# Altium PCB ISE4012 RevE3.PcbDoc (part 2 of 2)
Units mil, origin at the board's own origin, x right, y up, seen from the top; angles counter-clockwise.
Board outline 4950 x 3450 mil, 4 copper layers (Top Layer, InternalPlane1, MidLayer1, Bottom Layer), stack 59 mil thick; 143 components, 94 nets, 413 pads, 604 vias.
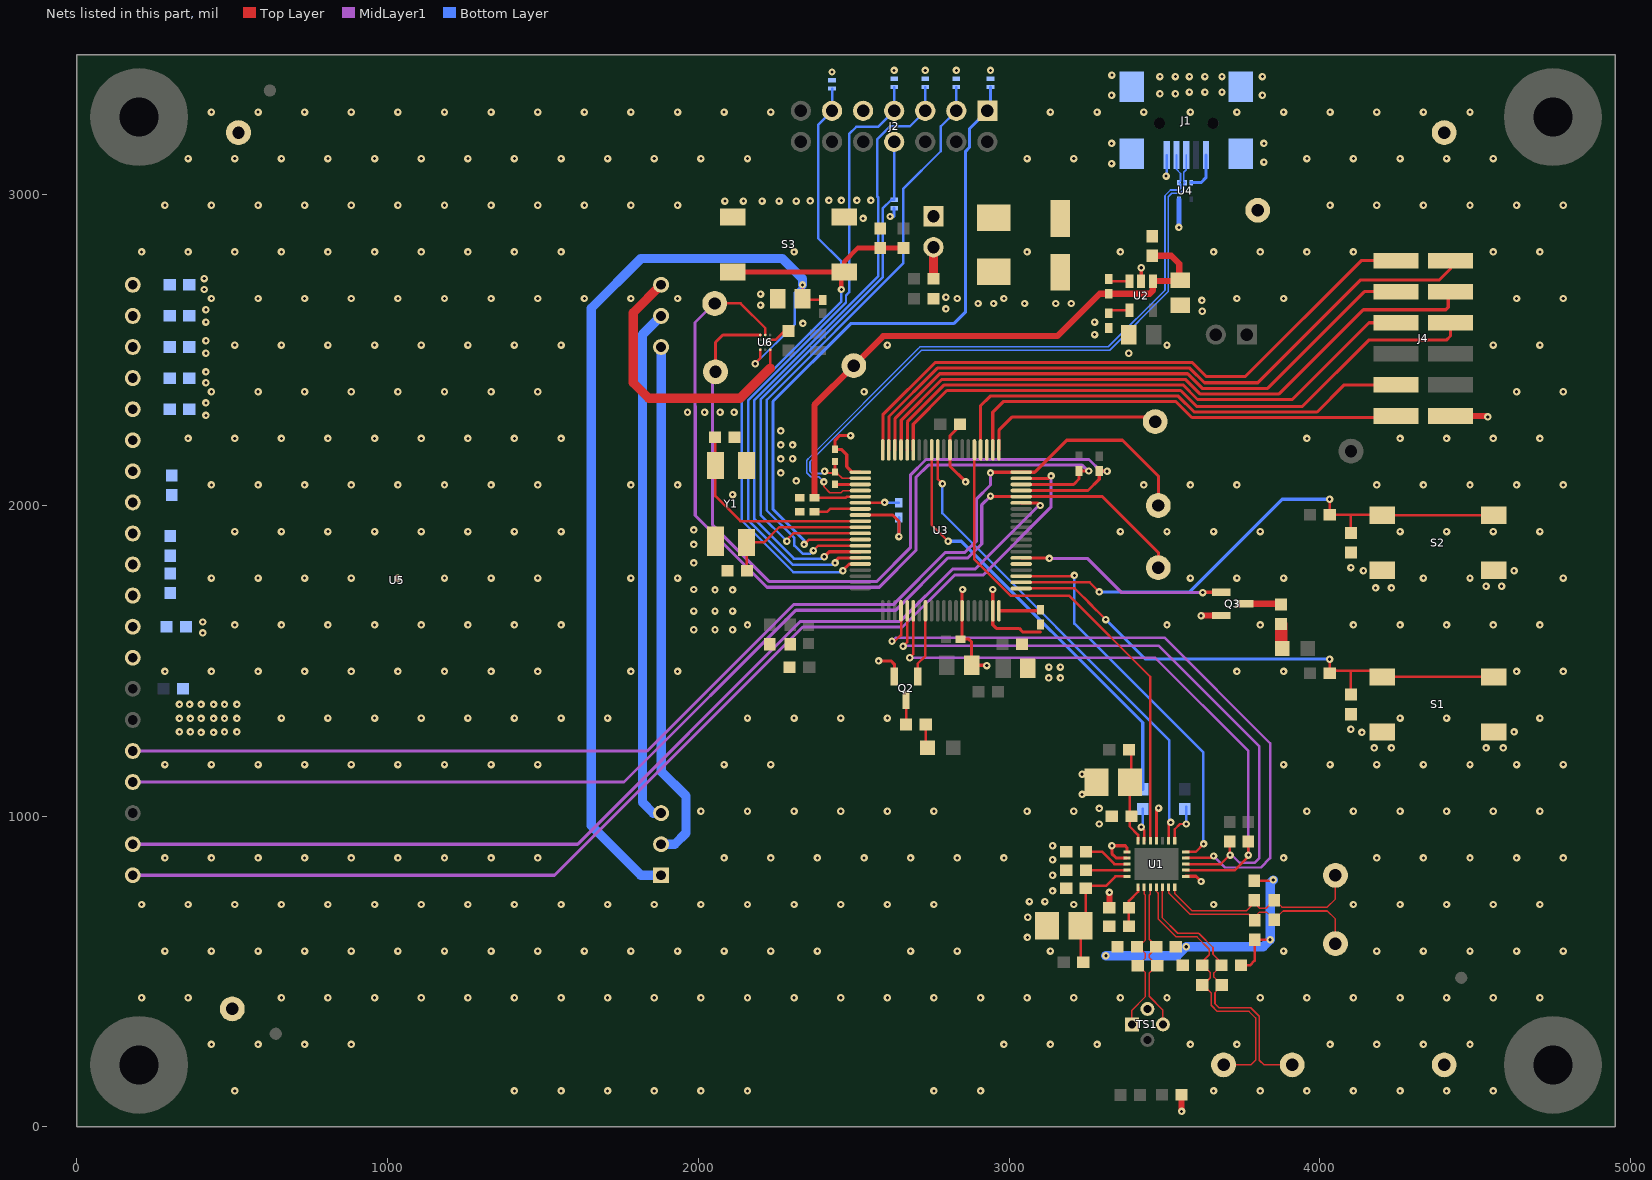
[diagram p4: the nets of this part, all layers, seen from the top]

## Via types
v1: diameter 24, hole 10, Top Layer to Bottom Layer, 393 vias
v2: diameter 24, hole 10, Top Layer to Bottom Layer, tented both sides, 210 vias
v3: diameter 24/24/24 (per signal layer), hole 10, Top Layer to Bottom Layer, tented both sides, 1 vias

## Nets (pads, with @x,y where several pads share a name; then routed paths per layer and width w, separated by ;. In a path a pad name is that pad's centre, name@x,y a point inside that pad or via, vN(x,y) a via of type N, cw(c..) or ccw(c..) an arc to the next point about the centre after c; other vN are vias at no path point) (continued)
GND: C1.2 C2.2 C3.2 C4.1 C5.2 C9.2 C10.2 C11.2 C12.2 C13.2 C14.2 C15.2 C16.2 C17.2 C18.2 C19.2 C20.2 C21.2 C22.2 C23.2 C24.2 C25.2 C26.2 C27.2 C28.2 C29.2 C30.2 C31.2 C35.2 C36.2 C37.2 C38.2 C39.2 C40.2 C41.2 C42.2 C43.2 C44.2 D1.2 D5.2 D6.2 D7.2 D8.2 D9.2 D10.2 J1.5 J1.6 J1.7 J1.8 J1.9 J2.9 J4.12 Q2.2 Q3.2 R16.1 R24.2 S1.3 S1.4 S2.3 S2.4 S3.3 S3.4 TP1.1 TP2.1 TP3.1 TP4.1 TS1.4 U1.8 U1.16 U1.20 U1.21 U2.2 U3.14 U3.19 U3.49 U3.61 U3.68 U4.3 U5.26 U5.33 U6.B3 U6.C2 Y1.2 Y1.4 | length 2288.9
  Top Layer w5: U6.C2@2214.5,2517.13 U6.B3@2230.25,2532.87
  Top Layer w8: U6.B3@2230.25,2532.87 2247.87,2532.87 2281.5,2566.5 C41.2@2295,2566.5
  Top Layer w10: v2(2490,2225) 2455,2225 2440,2210 R24.2@2440,2180.69 2460.27,2180.69 2477.27,2163.68 2477.27,2125 2495.26,2107.01 U3.61@2521.14,2107.01 ; U3.68@2521.14,1969.21 2625.79,1969.21 2645,1950 v2(2645,1900) ; v2(2580,1500) 2620,1500 2630.79,1489.21 Q2.2@2630.79,1449.48 ; C27.2@2841.5,2261 2841.5,2256.5 2809.53,2224.53 U3.49@2809.53,2178.86 2809.53,2126.47 v2(2860,2076) ; v2(2850,1729.61) 2848.9,1728.5 U3.14@2848.9,1661.14 2848.9,1575.28 C28.2@2843.62,1570 2870.5,1570 2879,1561.5 C29.2@2879,1486 2923.5,1486 v2@2928,1481.5 ; v2(2947.32,1729.61) U3.19@2947.32,1661.14 2947.32,1616 2958.82,1604.5 3032,1604.5 3043.12,1593.38 3101,1593.38 ; U1.21@3379.45,865.75 3344.25,865.75 3330.5,879.5 v2(3330.5,905) 3373.5,905 3379.45,899.05 U1.20@3379.45,885.43 ; U2.2@3425,2722.24 v2(3425,2765) ; U1.16@3473.94,920.87 3473.94,1018.94 v2(3481,1026) ; U1.8@3568.43,806.69 3601.15,806.69 v2(3617.84,790)
  Top Layer w20: C5.2@3322.44,706.06 3322.5,706.13 v2(3322.5,755) ; C44.2@3554.5,104 3555,103.5 v2(3555,50) ; v2(3617.5,1645) 3618.6,1646.1 Q3.2@3682.6,1646.1 ; J4.12@4420.5,2288 4537,2288 v2(4540,2285)
  Bottom Layer w10: v2(2617.1,2930) 2628.5,2930 2630,2931.5 D9.2@2630,2956.61 ; v2(2645,1900) C24.2@2645,1961.38 ; U4.3@3586.19,3039.07 3617.35,3039.07 3632.99,3054.71 J1.5@3632.99,3127.64
  other v1: 508,116 1408,116 1558,116 1708,116 1858,116 2008,116 2158,116 2758,116 2908,116 3658,116 3808,116 3958,116 4108,116 4258,116 4408,116 4558,116 433,266 583,266 733,266 883,266 2983,266 3133,266 3283,266 3583,266 3733,266 4033,266 4183,266 4333,266 4483,266 208,416 358,416 658,416 808,416 958,416 1108,416 1258,416 1408,416 1558,416 1708,416 1858,416 2008,416 2158,416 2308,416 2458,416 2608,416 2758,416 2908,416 3058,416 3208,416 3358,416 3508,416 3808,416 3958,416 4108,416 4258,416 4408,416 4558,416 4708,416 283,566 433,566 583,566 733,566 883,566 1033,566 1183,566 1333,566 1483,566 1633,566 1783,566 1933,566 2083,566 2233,566 2383,566 2683,566 2833,566 3133,566 3883,566 4183,566 4333,566 4483,566 4633,566 4783,566 208,716 358,716 508,716 658,716 808,716 958,716 1108,716 1258,716 1408,716 1558,716 1708,716 1858,716 2008,716 2158,716 2308,716 2458,716 2608,716 2758,716 3208,716 3658,716 4108,716 4258,716 4408,716 4558,716 4708,716 283,866 433,866 583,866 733,866 883,866 1033,866 1183,866 1333,866 1483,866 2083,866 2233,866 2383,866 2533,866 2683,866 2833,866 2983,866 3883,866 4183,866 4333,866 4483,866 4633,866 4783,866 2008,1016 2158,1016 2308,1016 2458,1016 2608,1016 2758,1016 3058,1016 3208,1016 3958,1016 4108,1016 4258,1016 4408,1016 4558,1016 4708,1016 283,1166 433,1166 583,1166 733,1166 883,1166 1033,1166 1183,1166 1333,1166 1483,1166 2083,1166 2233,1166 3883,1166 4033,1166 4183,1166 4333,1166 4483,1166 4633,1166 4783,1166 658,1316 808,1316 958,1316 1108,1316 1258,1316 1408,1316 1558,1316 1708,1316 2158,1316 2308,1316 2458,1316 2608,1316 4258,1316 4408,1316 4708,1316 283,1466 433,1466 583,1466 733,1466 883,1466 1033,1466 1183,1466 1333,1466 1483,1466 1783,1466 1933,1466 3733,1466 3883,1466 4633,1466 4783,1466 508,1616 658,1616 808,1616 958,1616 1108,1616 1258,1616 1408,1616 1558,1616 2158,1616 3508,1616 3808,1616 4108,1616 4258,1616 4408,1616 4558,1616 4708,1616 433,1766 583,1766 733,1766 883,1766 1033,1766 1183,1766 1333,1766 1483,1766 1783,1766 1933,1766 3583,1766 3733,1766 3883,1766 4333,1766 4483,1766 4783,1766 508,1916 658,1916 808,1916 958,1916 1108,1916 1258,1916 1408,1916 1558,1916 3358,1916 3508,1916 3658,1916 3808,1916 4258,1916 4408,1916 4558,1916 4708,1916 433,2066 583,2066 733,2066 883,2066 1033,2066 1183,2066 1333,2066 1483,2066 1783,2066 1933,2066 3433,2066 3583,2066 3733,2066 4183,2066 4333,2066 4483,2066 4633,2066 4783,2066 358,2216 508,2216 658,2216 808,2216 958,2216 1108,2216 1258,2216 1408,2216 1558,2216 3958,2216 4258,2216 4408,2216 4558,2216 4708,2216 433,2366 583,2366 733,2366 883,2366 1033,2366 1183,2366 1333,2366 1483,2366 2533,2366 4633,2366 4783,2366 508,2516 658,2516 808,2516 958,2516 1108,2516 1258,2516 1408,2516 1558,2516 2608,2516 3508,2516 4558,2516 4708,2516 433,2666 583,2666 733,2666 883,2666 1033,2666 1183,2666 1333,2666 1483,2666 1633,2666 1783,2666 1933,2666 2833,2666 2983,2666 3733,2666 3883,2666 4633,2666 4783,2666 208,2816 358,2816 508,2816 658,2816 808,2816 958,2816 1108,2816 1258,2816 1408,2816 1558,2816 2308,2816 3058,2816 3358,2816 3658,2816 3808,2816 3958,2816 4108,2816 4558,2816 4708,2816 283,2966 433,2966 583,2966 733,2966 883,2966 1033,2966 1183,2966 1333,2966 1483,2966 1633,2966 1783,2966 1933,2966 4033,2966 4183,2966 4333,2966 4483,2966 4633,2966 4783,2966 358,3116 508,3116 658,3116 808,3116 958,3116 1108,3116 1258,3116 1408,3116 1558,3116 1708,3116 1858,3116 2008,3116 2158,3116 3058,3116 3208,3116 3958,3116 4108,3116 4258,3116 4408,3116 4558,3116 433,3266 583,3266 733,3266 883,3266 1033,3266 1183,3266 1333,3266 1483,3266 1633,3266 1783,3266 1933,3266 2083,3266 2233,3266 3133,3266 3283,3266 3433,3266 3583,3266 3733,3266 3883,3266 4033,3266 4183,3266 4333,3266 4483,3266
  other v2: 3058.5,610 3060,675 3065,725 3115,725 3140,760 3140,810 3140,860 3140,905 3290,975 3290,1025 3235,1070 3235,1135 4175,1220 4230,1220 4535,1220 4590,1220 400,1270 440,1270 4135,1270 330,1271.42 365,1271.42 475,1271.42 515,1271.42 4625,1271.42 4100,1280 330,1315 365,1315 400,1315 440,1315 475,1315 515,1315 330,1360 362.5,1360 400,1360 440,1360 475,1360 515,1360 3127.32,1445 3165,1445 3128.08,1480 3165,1480 2928,1484.5 405,1590 1985,1600 2053.5,1600 2110,1600 405,1625 1985,1660 2053.5,1660 2110,1660 2053.5,1728.5 2110,1728.5 1985,1729.61 4179.45,1735 4230,1735 4535,1740 4585,1740 4140,1790 4625,1790 4100,1800 1985,1815 1985,1875 1985,1921.5 2110,2035 2315,2079 2265,2105 2265,2150 2303.43,2150.37 2265,2195 2303.43,2195 2265,2240 415,2290 1965,2300 2020,2300 2070,2300 2115,2300 415,2330 415,2395 415,2430 415,2490 3385,2490 415,2530 3275,2550 2336,2586 415,2590 3275,2590 3621.28,2625 415,2630 2796.38,2632.5 2200,2645 2900,2650 2950,2650 3050,2650 3150,2650 3200,2650 3620,2660 2796.38,2670 2200,2680 410,2695 410,2730 2530,2923.61 2085,2979.52 2145,2979.52 2205,2979.52 2260,2979.52 2315,2979.52 2360,2980 2420,2981.57 2460,2981.57 2510,2981.57 2555,2981.57 3330,3100 3820,3105 3330,3165 3820,3165 3330,3320 3815,3320 3485,3325 3535,3325 3580,3330 3630,3330 3685,3330 3485,3380 3535,3380 3580,3380 3630,3380 3685,3380 3815,3380 3330.5,3385 2430,3395 2630,3400 2730,3400 2830,3400 2940,3400
ILED: U5.20 U6.D3 | length 913.4
  Top Layer w8: 2230.75,2441.75 U6.D3@2230.75,2501.38
  Top Layer w30: U5.20@1880,2710 1790,2620 1790,2395 1840,2345 1985,2345 2134,2345 2230.75,2441.75
INN1: C6.2 R5.1 TS1.3 U1.3 | length 505
  Top Layer w5: U1.3@3454.25,771.26 3454.25,749.25 3450.5,745.5 3450.5,604.5 3475.5,579.5 3450.5,554.5 3450.5,545 C6.2@3476.5,519 3474,519 3450.5,495.5 3450.5,420.5 3495,376 TS1.3@3495,330
INN2: C7.2 R7.1 TP5.1 U1.5 | length 940.2
  Top Layer w5: U1.5@3493.62,771.26 3493.62,758.62 3492,757 3492,673.97 3542.47,623.5 3609.74,623.5 3611.74,621.5 3612,621.5 3656,577.5 3656,555.5 3687.5,524 3659,495.5 3659,482.5 C7.2@3684.5,457 3684.5,454.5 3662.5,432.5 3662.5,396.5 3675,384 3777.5,384 3805,356.5 3805,215 3820,200 TP5.1@3911,200
INN3: C8.2 R9.1 TP7.1 U1.7 | length 693
  Top Layer w5: U1.7@3532.99,771.26 3532.99,751.01 3587.5,696.5 3765,696.5 R9.1@3789,720.5 ; R9.1@3789,729.5 R9.1@3789,720.5 ; TP7.1@4050,810 4050,733.5 4024,707.5 3878,707.5 3856,729.5 C8.2@3853,729.5 3827,703.5 3806,703.5 R9.1@3789,720.5
INP1: C6.1 R4.1 TS1.1 U1.2 | length 501.9
  Top Layer w5: TS1.1@3395,330 3395,376 3438.5,419.5 3438.5,497.5 3417,519 C6.1@3413.5,519 3438.5,544 3438.5,558 3416.5,580 3438.5,602 3438.5,745.5 3434.57,749.43 U1.2@3434.57,771.26
INP2: C7.1 R6.1 TP6.1 U1.4 | length 939
  Top Layer w5: U1.4@3473.94,771.26 3473.94,758.06 3480,752 3480,669 3537.5,611.5 3604.77,611.5 3644,572.27 3644,554.5 3621.5,532 R6.1@3621.5,520 3624,520 3647,497 3647,480 C7.1@3624,457 ; C7.1@3621.5,457 C7.1@3624,457 ; TP6.1@3690,200 3778,200 3793,215 3793,350.86 3771.86,372 3670,372 3650.5,391.5 3650.5,431.5 3625,457 C7.1@3624,457
INP3: C8.1 R8.1 TP8.1 U1.6 | length 719.6
  Top Layer w5: U1.6@3513.31,771.26 3513.31,753.19 3582,684.5 3771,684.5 R8.1@3790,665.5 3790,675.5 3806,691.5 3828,691.5 C8.1@3853,666.5 3881.5,695 4024,695 4050,669 TP8.1@4050,590
LED_CA1: U5.2 U5.18 | length 1692
  Bottom Layer w30: U5.2@1880,910 1924,910 1960,946 1960,1065 1880,1145 U5.18@1880,2510
LED_CA2: U5.3 U5.19 | length 1664.4
  Bottom Layer w30: U5.3@1880,1010 1855,1010 1820,1045 1820,2550 U5.19@1880,2610
LIGHT_INT: U3.25
NCS_DISP: U3.39 U5.40 | length 3640.8
  Top Layer w10: U3.39@3038.86,2087.32 3127.32,2087.32 v2(3135,2095)
  MidLayer1 w10: U5.40@180,810 1537,810 2336,1609 2657,1609 2824,1776 2915.64,1776 3133.64,1994 3135,1994 v2@3135,2090
NetC1_1: C1.1 C3.1 L1.1 U1.24 | length 393.4
  Top Layer w8: L1.1@3238.5,530 3230.13,538.36 C1.1@3230.13,648 3246.5,664.36 C3.1@3246.5,768 ; C3.1@3246.93,776.06 3311.06,776.06 3341.69,806.69 U1.24@3379.45,806.69
NetC2_1: C2.1 C4.2 R1.1 U1.19 | length 319.3
  Top Layer w8: R1.1@3393.5,1220 3393.5,1119.76 3379.8,1106.06 3388,1097.87 3388,967 3414.88,940.12 U1.19@3414.88,920.87
NetC5_1: C5.1 R2.2 U1.1 | length 137.4
  Top Layer w8: R2.2@3385.43,646.06 3385.43,727.43 3414.88,756.88 U1.1@3414.88,771.26
NetC9_1: C9.1 U1.23 | length 132.7
  Top Layer w8: C9.1@3246.93,826.06 3247.24,826.38 U1.23@3379.45,826.38
NetC10_1: C10.1 U1.22 | length 149.1
  Top Layer w8: C10.1@3246.93,886.06 3298.94,886.06 3338.94,846.06 U1.22@3379.45,846.06
NetC14_1: C14.1 U2.4 | length 71.4
  Top Layer w8: C14.1@3320,2618.62 3329.13,2627.76 U2.4@3387.6,2627.76
NetC24_1: C24.1 U3.66 | length 125
  Top Layer w8: U3.66@2521.14,2008.58 2598.08,2008.58 v2(2599.5,2010)
  Bottom Layer w8: v2(2599.5,2010) 2600.88,2008.62 C24.1@2645,2008.62
NetC32_1: C32.1 U5.31
NetC32_2: C32.2 C33.1 U5.30
NetC33_2: C33.2 U5.29
NetC34_1: C34.1 U5.28
NetC34_2: C34.2 U5.27
NetC35_1: C35.1 U5.32
NetC36_1: C36.1 U5.25
NetC37_1: C37.1 U5.24
NetC38_1: C38.1 U5.23
NetC39_1: C39.1 U5.22
NetC40_1: C40.1 U5.21
NetD2_2: D2.2 R23.2 | length 77.3
  Top Layer w8: R23.2@2731.5,1295 2731.5,1225.67 D2.2@2737.17,1220
NetD4_2: D4.2 R12.2 | length 80
  Top Layer w40: R12.2@3875,1618.5 3875,1543.66 D4.2@3878.66,1540
NetJ5_2: J5.2 L2.1 | length 101
  Top Layer w30: L2.1@2756.5,2730 J5.2@2756.5,2831
NetQ2_1: Q2.1 U3.8 | length 222.1
  Top Layer w8: Q2.1@2705.59,1449.48 2705.59,1490.59 2730.79,1515.79 U3.8@2730.79,1661.14
NetQ2_3: Q2.3 R23.1 | length 79.8
  Top Layer w8: Q2.3@2668.19,1374.68 2668.19,1295.32 R23.1@2668.5,1295
NetQ3_1: Q3.1 U3.26 | length 690.7
  Top Layer w10: U3.26@3038.86,1831.42 3128.08,1831.42 v2(3129.5,1830) ; v2(3623,1719.5) 3624.4,1720.9 Q3.1@3682.6,1720.9
  MidLayer1 w10: v2(3129.5,1830) 3251.5,1830 3362,1719.5 v2(3623,1719.5)
NetQ3_3: Q3.3 R12.1 | length 118.4
  Top Layer w20: Q3.3@3757.4,1683.5 3873,1683.5 R12.1@3875,1681.5
NetR10_1: R10.1 U1.13 | length 136.7
  Top Layer w8: U1.13@3532.99,920.87 3532.99,957.99 3550,975 v2(3570,975)
  Bottom Layer w8: v2(3570,975) R10.1@3570,1030.5
NetR11_1: R11.1 U1.18 | length 101.6
  Top Layer w8: v3@3430,960 3434.57,955.43 U1.18@3434.57,920.87
  Bottom Layer w8: v3(3425,965) 3430,970 R11.1@3430,1023.5
NetR18_1: R18.1 U2.3 | length 70.2
  Top Layer w8: R18.1@3320,2728.62 3326.38,2722.24 U2.3@3387.6,2722.24
NPWDNB: R13.1 U1.9 U3.6 | length 1956.3
  Top Layer w8: v2(2680,1510) 2691.42,1521.42 U3.6@2691.42,1661.14 ; U1.9@3568.43,826.38 3726.38,826.38 v2@3770,870 ; v2@3770,881 R13.1@3770,918.5
  MidLayer1 w8: v2(2680,1510) 3470,1510 3770,1210 v2@3770,881
  other v2: 3770,875
NRST_DISP: U3.35 U5.39 | length 3434.7
  Top Layer w10: U3.35@3038.86,2008.58 3091.42,2008.58 v2(3100,2000)
  MidLayer1 w10: U5.39@180,910 1611.54,910 2328.54,1627 2649.54,1627 2817.54,1795 2890,1795 v2@3097.5,2002.5
NRST_MSP: C30.1 D10.1 J2.11 R26.1 S3.1 S3.2 U3.76 | length 2690.1
  Top Layer w10: v2(2465,1790) 2465,1791.19 2484.77,1810.95 2520.36,1810.95 U3.76@2521.14,1811.73
  Top Layer w15: S3.2@2110.87,2751.42 S3.1@2469.13,2751.42 ; v2@2460,2700 2460,2742.28 S3.1@2469.13,2751.42 ; R26.1@2660,2828.5 C30.1@2585,2828.5 2513.5,2828.5 2469.13,2784.13 S3.1@2469.13,2751.42
  Bottom Layer w8: D10.1@2430,3341.61 J2.11@2430,3270 2385,3225 2385,2860 2460,2785 2460,2656 2140,2336 2140,1950.8 2305.8,1785 2460,1785 v2(2465,1790)
  other v2: 2460,2695
NRSTB: R14.1 U1.10 U3.5 | length 2064.6
  Top Layer w8: v2(2659,1547) 2671.73,1559.73 U3.5@2671.73,1661.14 ; U1.10@3568.43,846.06 3681.06,846.06 v2@3710,875 ; v2@3710,881 R14.1@3710,918.5
  MidLayer1 w8: v2(2659,1547) 2661,1549 3481,1549 3805,1225 3805,865 3790,850 3742,850 v2@3711,881
  other v2: 3711,875
OVP: C42.1 D3.1 U5.1 U6.D1 | length 3229.9
  Top Layer w8: v2(2183,2456) 2183,2458 2199.25,2474.25 U6.D1@2199.25,2501.38 ; v2(2335,2710) C42.1@2335,2665 2338.35,2661.65 D3.1@2400,2661.65
  Bottom Layer w8: v2(2183,2456) 2310,2583 2310,2685 v2(2335,2710)
  Bottom Layer w30: U5.1@1880,810 1815,810 1655,970 1655,2635 1815,2795 2270,2795 2335,2730 v2(2335,2710)
PUR_1: R25.1 U3.63 | length 73.8
  Top Layer w10: R25.1@2447.32,2067.64 U3.63@2521.14,2067.64
SCL: R21.1 TP10.1 U3.38 U6.A2 | length 2847.5
  Top Layer w8: TP10.1@2050,2650 2136,2650 2215,2571 U6.A2@2215,2548.62
  Top Layer w10: U3.38@3038.86,2067.64 3207.64,2067.64 3225,2085 R21.1@3225,2111.38 3253.62,2111.38 v2@3255,2110
  MidLayer1 w10: TP10.1@2050,2650 1989,2589 1989,2321.36 1990,2320.36 1990,1968 2221,1737 2582,1737 2700,1855 2700,2090 2740,2130 3235,2130 v2@3255,2110
  other v2: 3256,2111
SCL_DISP: TP12.1 U3.36 U5.37 | length 3878.6
  Top Layer w10: v2(2940,2030) 2941.73,2028.27 U3.36@3038.86,2028.27 3300.24,2028.27 3480,1848.5 TP12.1@3480,1800
  MidLayer1 w10: U5.37@180,1110 1760.63,1110 2313.63,1663 2634.63,1663 2802.63,1831 2867,1831 2912,1876 2912,2002 v2(2940,2030)
SCLK_AFE: U1.17 U3.45 | length 1602.6
  Top Layer w8: U3.45@2888.27,2178.86 2888.27,1826.73 3005,1710 3193,1710 3454,1449 3454,921.12 U1.17@3454.25,920.87
SDA: R20.1 TP9.1 U3.37 U6.A1 | length 2725
  Top Layer w10: TP9.1@2055,2450 2055,2525 2078.62,2548.62 U6.A1@2199.25,2548.62 ; U3.37@3038.86,2047.95 3253.95,2047.95 3290,2084 R20.1@3290,2111.38 3313.62,2111.38 v2(3315,2110)
  MidLayer1 w10: TP9.1@2055,2450 2045,2440 2045,1938.46 2228.46,1755 2573,1755 2682,1864 2682,2097.46 2732.54,2148 3257,2148 3295,2110 v2(3315,2110)
SDI_AFE: U1.14 U3.51 | length 1569.8
  Top Layer w8: U3.51@2770.16,2178.86 2770.16,2084.84 v2(2785,2070) ; U1.14@3513.31,920.87 v2@3513.31,983.31
  Bottom Layer w8: v2(2785,2070) 2785,1975 3515,1245 v2@3515,980
  other v2: 3520,980
SDO_AFE: R11.2 U3.52 | length 1398.9
  Top Layer w8: U3.52@2750.47,2178.86 2750.47,1938.07 v2(2803.54,1885)
  Bottom Layer w10: v2(2803.54,1885) 2846.42,1885 3430,1301.42 R11.2@3430,1086.5
SI_DISP: TP11.1 U3.40 U5.36 | length 3958.8
  Top Layer w10: v2(2940,2105) 2942.01,2107.01 U3.40@3038.86,2107.01 3082.01,2107.01 3185,2210 3365,2210 3480,2095 TP11.1@3480,2000
  MidLayer1 w10: U5.36@180,1210 1835.18,1210 2306.18,1681 2627.18,1681 2795.18,1849 2858,1849 2894,1885 2894,2020 2940,2066 v2(2940,2105)
SOMI_D: TP14.1 U3.41 | length 590
  Top Layer w10: U3.41@2967.01,2178.86 2967.01,2241.75 3010.26,2285 3455,2285 TP14.1@3470,2270
SYNC: U1.11 U3.4 | length 2150.2
  Top Layer w8: v2(2623,1563) 2632,1563 2652.05,1583.05 U3.4@2652.05,1661.14 ; U1.11@3568.43,865.75 3651.75,865.75 v2(3658,872)
  MidLayer1 w8: v2(2623,1563) 2635,1575 3500,1575 3840,1235 3840,865 3810,835 3695,835 v2(3658,872)
TB0.0: J4.6 U3.55 | length 2014.3
  Top Layer w10: U3.55@2691.42,2178.86 2691.42,2261.77 2799.64,2370 3551.91,2370 3602.91,2319 3944,2319 4157,2532 4407,2532 4420.5,2545.5 J4.6@4420.5,2588
TB0.1: J4.5 U3.56 | length 1834.5
  Top Layer w10: U3.56@2671.73,2178.86 2672.51,2179.64 2672.51,2268.97 2791.54,2388 3559.37,2388 3606.37,2341 3911,2341 4158,2588 J4.5@4245.5,2588
TB0.2: J4.4 U3.57 | length 2098.9
  Top Layer w10: U3.57@2652.05,2178.86 2652.83,2179.64 2652.83,2274.74 2784.09,2406 3566.82,2406 3613.82,2359 3869,2359 4140,2630 4405,2630 4413,2638 4413,2680.5 J4.4@4420.5,2688
TB0.3: J4.3 U3.58 | length 1922.1
  Top Layer w10: U3.58@2632.36,2178.86 2633.14,2179.64 2633.14,2280.51 2776.63,2424 3574.28,2424 3621.28,2377 3832,2377 4143,2688 J4.3@4245.5,2688
TB0.4: J4.2 U3.59 | length 2177.1
  Top Layer w10: U3.59@2612.68,2178.86 2613.46,2179.64 2613.46,2286.28 2769.18,2442 3581.73,2442 3628.73,2395 3800,2395 4131,2726 4385,2726 4420.5,2761.5 J4.2@4420.5,2788
TB0.5: J4.11 U3.42 | length 1456.8
  Top Layer w10: U3.42@2947.32,2178.86 2947.32,2300.32 2981,2334 3537,2334 3588,2283 4240.5,2283 J4.11@4245.5,2288
TB0.6: U3.43
TB0OUTH: J4.9 U3.44 | length 1549.7
  Top Layer w10: U3.44@2907.95,2178.86 2907.95,2320.95 2939,2352 3544.46,2352 3595.46,2301 3991,2301 4078,2388 J4.9@4245.5,2388
TBOCLK: J4.1 U3.60 | length 2008
  Top Layer w10: U3.60@2592.99,2178.86 2593.77,2179.64 2593.77,2292.05 2761.72,2460 3589.19,2460 3634.19,2415 3760,2415 4133,2788 J4.1@4245.5,2788
TCK: D8.1 J2.7 U3.75 | length 2063.3
  Top Layer w10: v2@2435,1815 2451.42,1831.42 U3.75@2521.14,1831.42
  Bottom Layer w8: v2(2440,1815) 2435,1810 2303.43,1810 2160,1953.43 2160,2337.62 2475,2652.62 2475,2676.06 2485,2686.06 2485,3195 2508,3218 2578,3218 J2.7@2630,3270 D8.1@2630,3346.61
TDI: D6.1 J2.3 U3.73 | length 1998.7
  Top Layer w8: v2(2370,1855) 2385.79,1870.79 U3.73@2521.14,1870.79
  Bottom Layer w8: v2(2370,1855) 2360,1845 2335,1845 2309,1871 2309,1894.94 2220,1983.94 2220,2340 2660,2780 2660,3020 2780,3140 2780,3220 J2.3@2830,3270 D6.1@2830,3346.61
TDO: D5.1 J2.1 U3.72 | length 2184.7
  Top Layer w8: v2(2340,1875) 2355.47,1890.47 U3.72@2521.14,1890.47
  Bottom Layer w10: v2(2340,1875) 2340,1887.98 2240,1987.98 2240,2335 2490,2585 2821.42,2585 2860,2623.58 2860,3139.92 2872.48,3152.4 2872.48,3212.48 J2.1@2930,3270 2940,3280 D5.1@2940,3346.61
TEST_MSP: D9.1 J2.8 U3.71 | length 1744.7
  Top Layer w8: 2292.5,1897.5 2305.16,1910.16 U3.71@2521.14,1910.16
  Bottom Layer w8: v2@2290,1880 v2(2285,1885) 2200,1970 2200,2340.85 2594,2734.85 2594,2956.68 2620.71,2983.39 D9.1@2630,2983.39 J2.8@2630,3170
TMS: D7.1 J2.5 U3.74 | length 2060.6
  Top Layer w10: v2(2405,1835) 2421.1,1851.1 U3.74@2521.14,1851.1
  Bottom Layer w8: v2(2405,1835) 2399,1829 2307.06,1829 2180,1956.06 2180,2339.23 2578,2737.23 2578,2991.1 2575,2994.1 2575,3177.9 2617.1,3220 2680,3220 J2.5@2730,3270 D7.1@2730,3346.61
USB_D_N: J1.2 U3.64 U4.1 | length 2118.8
  Top Layer w5.3: v2(2404,2076) 2404,2060 2423,2041 2459,2041 2465.95,2047.95 U3.64@2521.14,2047.95
  Bottom Layer w5.3: v2(2404,2076) 2401,2079 2387.3,2092.7 2361.73,2092.7 2348.7,2105.73 2348.7,2145.27 2352.48,2149.05 2352.48,2149.48 2708,2505 2708.06,2505 2713.36,2510.3 3319.13,2510.3 3501.6,2692.77 3501.6,2997.27 3519.33,3015 3546.51,3015 3551.51,3020 3551.51,3034.38 U4.1@3546.81,3039.07 3551.57,3043.83 3551.57,3068.43 3538.5,3081.5 J1.2@3538.5,3127.64
  Bottom Layer w8: v2@2401,2079 v2@2406,2084
USB_D_P: J1.3 R24.1 R25.2 U3.62 U4.2 | length 2104.5
  Top Layer w5.3: v2@2406.31,2104.69 R25.2@2440,2104.69 ; R25.2@2445.31,2104.69 2462.68,2087.32 U3.62@2521.14,2087.32
  Top Layer w10: v2@2406,2105 v2@2406.31,2104.69 ; R24.1@2440,2140.32 R25.2@2440,2107.69 2440,2104.69 R25.2@2445.31,2104.69
  Bottom Layer w5.3: v2(2406,2110) 2399,2103 2366,2103 2359,2110 2359,2141 2718,2500 3323.4,2500 3511.9,2688.5 3511.9,2993 3523.6,3004.7 3550.77,3004.7 3561.81,3015.73 3561.81,3034.38 U4.2@3566.5,3039.07 3561.87,3043.7 3561.87,3071.87 3570,3080 J1.3@3570,3127.64
USER_BUTTON1: C16.1 R19.1 S1.1 S1.2 U3.21 | length 1741
  Top Layer w8: U3.21@3038.86,1732.99 3211.01,1732.99 3267.76,1676.24 ; 3254.25,1689.75 v1(3311,1633) ; R19.1@4031.5,1460 v2(4031.5,1505) ; R19.1@4050.75,1469.25 4051.5,1468.5 4097.99,1468.5 4100,1466.5 C16.1@4100,1391.5 ; 4101.5,1468.5 4180.94,1468.5 S1.1@4200.87,1448.58 S1.2@4559.13,1448.58
  Bottom Layer w10: v1(3311,1633) 3438,1506 v2@4030.5,1506
USER_BUTTON2: C19.1 R22.1 S2.1 S2.2 U3.22 | length 1757
  Top Layer w8: U3.22@3038.86,1752.68 3259.32,1752.68 v1(3290,1722) ; R22.1@4031.5,1970 v2(4031.5,2020) ; R22.1@4040,1970 4100,1970 ; C19.1@4100,1911.5 4100,1970 ; S2.2@4559.13,1968.58 S2.1@4200.87,1968.58 4199.45,1970 4100,1970
  Bottom Layer w10: v1(3290,1722) 3581,1722 3879,2020 v2(4031.5,2020)
V18_1: C21.1 U3.67 | length 151.2
  Top Layer w8: C21.1@2373.62,1980 2415,1980 2423.9,1988.9 U3.67@2521.14,1988.9
VBUS: C17.1 D1.1 J1.1 J5.1 L3.1 TP13.1 U4.5 | length 160.1
  Bottom Layer w5.3: v2@3545,2895 v2@3546.81,2896.81
  Bottom Layer w8: v2(3505,3060) 3507.01,3062.01 J1.1@3507.01,3127.64
  Bottom Layer w15: v2@3546.81,2896.81 U4.5@3546.81,2985.93
  other v2: 3546.51,2895
VBUS_FLT: C13.1 C23.1 L3.2 R18.2 TP15.1 U2.1 U3.65 | length 1959.7
  Top Layer w8: C23.1@2376.81,2028.19 2380,2025 2474,2025 2477.27,2028.27 U3.65@2521.14,2028.27 ; C13.1@3547.24,2722.24 C13.1@3550,2725
  Top Layer w20: C23.1@2373.62,2025 2373.62,2323.62 TP15.1@2500,2450 2595,2545 3155,2545 3291.38,2681.38 R18.2@3320,2681.38 3452.38,2681.38 3462.4,2691.4 U2.1@3462.4,2722.24 3547.24,2722.24 3547.24,2777.76 3521.5,2803.5 L3.2@3460,2803.5
VCM: R2.1 R4.2 R5.2 R6.2 R7.2 R8.2 R9.2 | length 975.9
  Top Layer w8: R7.2@3746.5,520 3774.5,520 3790,535.5 R8.2@3790,602.5 v2(3840,602.5) ; R9.2@3789,792.5 3847.5,792.5 v2(3850,795)
  Bottom Layer w30: v2(3311.06,551) 3541,551 v2(3570,580) 3817.5,580 v2(3840,602.5) 3840,785 v2(3850,795)
VCORE1: C22.1 U3.20 | length 134
  Top Layer w10: U3.20@2967.01,1661.14 C22.1@3101,1661.14
XCLK: U1.12 U3.23 | length 1284.8
  Top Layer w8: U3.23@3038.86,1772.36 3207.36,1772.36 v2(3210,1775) ; U1.12@3568.43,885.43 3600.43,885.43 v2(3626,911)
  Bottom Layer w8: v2(3210,1775) 3210,1620 3625,1205 3625,911 v2@3619,905
XT2IN1: C18.1 U3.69 Y1.1 | length 690.1
  Top Layer w8: C18.1@2053.5,2220 2053.5,2130.51 Y1.1@2055,2129.02 2055,2030 2135.47,1949.53 U3.69@2521.14,1949.53
XT2OUT1: C20.1 U3.70 Y1.3 | length 478
  Top Layer w8: C20.1@2156.5,1790 2155,1791.5 Y1.3@2155,1880.98 2210.98,1880.98 2259.84,1929.84 U3.70@2521.14,1929.84
pads on no net: FID1.1 FID2.1 FID3.1 H1.1 H2.1 H3.1 H4.1 J1.4 J1.10 J1.11 J2.2 J2.6 J2.10 J2.12 J2.13 J2.14 J4.7 J4.8 J4.10 SH-J1.0 SH-J2.0 U1.25 U3.1 U3.2 U3.3 U3.7 U3.9 U3.10 U3.12 U3.13 U3.15 U3.16 U3.17 U3.24 U3.27 U3.28 U3.32 U3.46 U3.47 U3.48 U3.53 U3.54 U3.80 U4.4 U6.B2 U6.D2

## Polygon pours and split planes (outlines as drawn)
+3P3V on MidLayer1 "GND" (solid, remove dead copper, pour order 4): 3038.86,1545 3085,1545 3085,1300 3340,1300 3340,1180 2935,1180 2935,1430 3038.86,1430
GND on MidLayer1 "GND" (solid, remove dead copper, pour order 6): 60,3400 60,50 70,40 4900,40 4900,3400
GND on InternalPlane1 (split plane): 4929.9,20.1 20.1,20.1 20.1,3429.9 4929.9,3429.9

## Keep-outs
Keep-Out Layer:
  lines w10: -5,0 ccw(c0,0) 0,-5 ; -5,0 ccw(c0,0) 0,-5 ; -5,0 ccw(c0,0) 0,-5 ; -5,0 ccw(c0,0) 0,-5 ; -5,0 ccw(c0,0) 0,-5 ; -5,0 ccw(c0,0) 0,-5 ; -5,0 -5,3450 ; -5,3450 cw(c0,3450) 0,3455 ; -5,3450 cw(c0,3450) 0,3455 ; -5,3450 cw(c0,3450) 0,3455 ; -5,3450 cw(c0,3450) 0,3455 ; -5,3450 cw(c0,3450) 0,3455 ; -5,3450 cw(c0,3450) 0,3455 ; 0,-5 4950,-5 ; 0,3455 4950,3455 ; 4950,-5 ccw(c4950,0) 4955,0 ; 4950,-5 ccw(c4950,0) 4955,0 ; 4950,-5 ccw(c4950,0) 4955,0 ; 4950,-5 ccw(c4950,0) 4955,0 ; 4950,-5 ccw(c4950,0) 4955,0 ; 4950,-5 ccw(c4950,0) 4955,0 ; 4950,3455 cw(c4950,3450) 4955,3450 ; 4950,3455 cw(c4950,3450) 4955,3450 ; 4950,3455 cw(c4950,3450) 4955,3450 ; 4950,3455 cw(c4950,3450) 4955,3450 ; 4950,3455 cw(c4950,3450) 4955,3450 ; 4950,3455 cw(c4950,3450) 4955,3450 ; 4955,0 4955,3450
  text ".Layer_Name" at 577,-858.49 h60

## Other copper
Top Layer:
  region net GND: 2731.5,2690 2731.5,2616.5 3196.5,2616.5 3225,2645 3225,2828.5 3216.5,2820 2829.21,2820 2829.21,2690
  region net +5V: 2269.5,2520 2269.5,2474.25 2434.39,2474.25 2600.14,2640 2720,2640 2720,2765 2645,2765 2645,2745 2420,2520
  region net +3P3V: 300,1440 300,1275 121.5,1275 121.5,1440
  region net GND: 3190.15,1640 3020,1640 3020,1421 3189.99,1421
  region net +3P3V: 2947.32,1575.28 3010,1575.28 3010,1397.4 3146.41,1280 3340,1280 3340,1185 3115,1185 2947.32,1352.68
  region net GND: 4060.55,1355.79 4060.55,1185 4645.55,1185 4645.55,1355
  region net GND: 4065,1870.79 4065,1700 4650,1700 4650,1870
  region net GND: 3515,2675 3515,2605 3650,2605 3650,2675
  region net GND: 3260,2605 3296.38,2605 3296.38,2588 3430,2588 3430,2475 3260,2475
  region net GND: 2050,3000 2050,2900 2550,2900 2550,2865 2625,2865 2625,3000
  region net GND: 2281.5,2697 2180,2697 2180,2630 2281.5,2630
  region net GND: 2270,2586.45 2270,2540 2350,2540 2350,2600 2283.55,2600
  region net GND: 2346,1965 2159.97,1965 2100,2025.09 2100,2240 2090,2250 1985,2250 1985,1935 2100,1935 2100,1830 2125,1830 2125,1575.28 2326.38,1575.28 2326.38,1445 1935,1445 1935,2315 2221.1,2315 2346,2190.1
  region net GND: 3330,1160 3330,1045 3358.5,1045 3358.5,930 3210,930 3210,729.5 3209.35,728.85 3175.5,728.85 3175.5,570 3050,570 3050,1160
  region net VCM: 3515,600 3515,500 3580,500 3580,600
  region net VBUS: 2720,2985 2720,2882.5 2871.5,2882.5 2871.5,2860 3441.3,2860 3441.3,2840 3870,2840 3870,3020 3700,3020 3700,2900 3560,2900 3560,2909 3530,2909 3530,2900 3500,2900 3500,3040 3520,3040 3520,3180 3450,3180 3450,2985
  region net VCM: 3295,670 3350,670 3350,605 3380,605 3380,535 3295,535
  text ".Layer_Name" at 582,-856.49 h60
MidLayer1:
  text ".Layer_Name" at 579,-856.49 h60
Bottom Layer:
  region net NetC32_2: 321.5,1855 321.5,1765 126.5,1765 126.5,1855
  region net NetC32_1: 320,1750 320,1660 125,1660 125,1750
  region net +3P3V: 300,1440 300,1275 121.5,1275 121.5,1440
  region net NetC35_1: 316.5,1650 316.5,1560 121.5,1560 121.5,1650
  region net NetC33_2: 346.5,1961.5 346.5,1871.5 126.5,1871.5 126.5,1961.5
  region net NetC34_1: 346.5,2060 346.5,1970 125,1970 125,2060
  region net NetC34_2: 346.5,2165 346.5,2075 126.5,2075 126.5,2165
  region net NetC36_1: 320,2350 320,2260 125,2260 125,2350
  region net NetC37_1: 320,2450 320,2360 125,2360 125,2450
  region net NetC38_1: 320,2550 320,2460 125,2460 125,2550
  region net NetC39_1: 320,2650 320,2560 125,2560 125,2650
  region net NetC40_1: 320,2750 320,2660 125,2660 125,2750
  region net GND: 121.5,1550 121.5,1450 315,1450 315,1250 550,1250 550,2750 335,2750 335,2250 400,2250 400,1650 325,1650 325,1550
  region net GND: 2410,3360 2480,3360 2480,3235 2570,3235 2570,3364 3250,3364 3250,3050 3450,3050 3450,3300 3700,3300 3700,3200 3620,3200 3620,3050 3850,3050 3850,3419 2410,3419
  text "UL94V-0" at 2662,113 h60
  text "MADE IN U.S." at 1250,86.5 h60
  text ".Layer_Name" at 577,-858.49 h60
InternalPlane1 (plane layer: these items are gaps in the copper):
  text ".Layer_Name" at 577,-858.49 h60

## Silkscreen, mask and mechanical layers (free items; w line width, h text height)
Top Overlay:
  text "GND" at 4328.5,3130 h70 r90
  text "GND" at 693,3128.5 h70 r90
  text "VBUS" at 3979.5,2858.5 h70 r90
  text "RESET" at 2047.5,2741.5 h70 r90
  text "SCL" at 2169.5,2591.5 h70 r90
  text "SDA" at 2170,2340 h70 r90
  text "VBUS_FLT" at 2660,2292.05 h60 r90
  text "SOMI_D" at 3658,2160 h65 r90
  text "+3P3V" at 4028,2085.5 h70 r90
  text "SI_D" at 3650,1949.53 h70 r90
  text "SCL_D" at 3400,1710 h70 r90
  text "INN3" at 4223.5,737 h70 r90
  text "INP3" at 4222.5,531.5 h70 r90
  text ".CopyrightYear" at 1540,420 h60
  text "©" at 1440,410 h105
  text "GND" at 433,310.5 h70 r90
  text "GND" at 4328.5,134 h70 r90
  text ".Layer_Name" at 577,-858.49 h60
Bottom Overlay:
  rectangle: 1179,150 1479,250
  text ".PCB_Rev" at 1108,160 h60
  text ".PRJ_Number" at 2145,160 h60
  text ".Layer_Name" at 577,-858.49 h60
Top Paste:
  text ".Layer_Name" at 577,-858.49 h60
Bottom Paste:
  text ".Layer_Name" at 577,-858.49 h60
Top Solder:
  text ".Layer_Name" at 577,-858.49 h60
  text ".Layer_Name" at 577,-858.49 h60
Bottom Solder:
  text ".Layer_Name" at 577,-858.49 h60
Drill Guide:
  text ".Layer_Name" at 577,-858.49 h60
M1 Board Outline:
  the board outline again, w10
  text ".Layer_Name" at 577,-858.49 h60
M2 Board Dimensions:
  rectangle: -0.5,-285.5 124.5,-160.5
  rectangle: 124.5,-410.5 499.5,-285.5
  lines w7: -0.5,-285.5 999.5,-285.5 ; 124.5,-410.5 124.5,-160.5 ; 249.5,-410.5 249.5,-160.5 ; 499.5,-410.5 499.5,-160.5 ; 749.5,-410.5 749.5,-160.5 ; -0.5,-410.5 999.5,-410.5 999.5,-160.5 -0.5,-160.5 -0.5,-410.5
  lines w10: -0.5,-475.5 -0.5,-455.5 ; 59.5,-485.5 -0.5,-465.5 ; 59.5,-445.5 -0.5,-465.5 ; 223.58,-465.5 -0.5,-465.5 ; 775.42,-465.5 999.5,-465.5 ; 939.5,-485.5 999.5,-465.5 ; 939.5,-445.5 999.5,-465.5 ; 999.5,-475.5 999.5,-455.5
  text "1000 (mil)" at 233.58,-501.49 h60
  text ".Layer_Name" at 577,-858.49 h60
M3 3D STEP Top:
  text ".Layer_Name" at 577,-858.49 h60
M4 3D STEP Bottom:
  text ".Layer_Name" at 577,-858.49 h60
M5 Assembly Top:
  lines w10: -292,-930.17 6308,-930.17 ; -292,-726.83 6310,-726.83 ; -292,-523.5 -292,-1133.5 3713,-1133.5 6310,-1133.5 6310,-523.5 -291.5,-523.5 -291.5,-1133.5 1284,-1133.5 ; 2173,-1133.5 2173,-523.5 ; 3440,-726.83 3440,-523.5 ; 4280,-726.83 4280,-523.5 ; 4902,-1140 4902,-937.17
  text "COMPONENTS MARKED 'DNP' SHOULD NOT BE POPULATED." at 1153.5,-318.5 h60
  text "ASSEMBLY VARIANT:" at 1153,-434 h60
  text ".VariantName" at 2189,-434 h60
  text "PCB VIEWED FROM TOP SIDE" at -228.5,-655.67 h60
  text "BOARD #:" at 2248,-655.67 h60
  text ".PRJ_Number" at 2793.5,-655.67 h60
  text "REV:" at 3638,-655.67 h60
  text ".PCB_Rev" at 3929.5,-655.67 h60
  text "SVN REV:" at 4476,-655.67 h60
  text ".VersionControl_RevNumber" at 4982,-655.67 h60
  text "IGNORE ->" at -228.5,-858.49 h60
  text "PLOT NAME =" at -228.5,-1064.34 h60
  text ".plot_File_Name" at 577,-1064.34 h60
  text "GENERATED    :" at 2250,-1064.34 h60
  text ".Print_Date" at 3119.5,-1064.34 h60
  text ".Print_Time" at 3848.5,-1064.34 h60
  text "TEXAS INSTRUMENTS" at 5113,-1064.34 h60
M6 Assembly Bottom:
  lines w10: -292.5,-727.33 6309.5,-727.33 ; -290.5,-930.67 6309.5,-930.67 ; 1115.5,-1140.5 1115.5,-937.67 ; 1737.5,-727.33 1737.5,-524 ; 2577.5,-727.33 2577.5,-524 ; 3844.5,-1134 3844.5,-524 ; 4733.5,-1134 6309,-1134 6309,-524 -292.5,-524 -292.5,-1134 2304.5,-1134 6309.5,-1134 6309.5,-524
  text "COMPONENTS MARKED 'DNP' SHOULD NOT BE POPULATED." at 6102,-318 h60
  text ".VariantName" at 5058,-434 h60
  text "ASSEMBLY VARIANT:" at 6097,-434 h60
  text ".VersionControl_RevNumber" at 1035.5,-656.17 h60
  text "SVN REV:" at 1541.5,-656.17 h60
  text ".PCB_Rev" at 2088,-656.17 h60
  text "REV:" at 2379.5,-656.17 h60
  text ".PRJ_Number" at 3224,-656.17 h60
  text "BOARD #:" at 3769.5,-656.17 h60
  text "PCB VIEWED FROM BOTTOM SIDE" at 6246,-656.17 h60
  text "IGNORE ->" at 2547.85,-858.49 h60
  text "TEXAS INSTRUMENTS" at 904.5,-1064.84 h60
  text ".Print_Time" at 2169,-1064.84 h60
  text ".Print_Date" at 2898,-1064.84 h60
  text "GENERATED    :" at 3767.5,-1064.84 h60
  text ".plot_File_Name" at 5440.5,-1064.84 h60
  text "PLOT NAME =" at 6246,-1064.84 h60
M9 Title Sheet:
  drawing of 57 lines, arcs and shapes, not listed
  text "1" at 739.84,8036.5 h70
  text "2" at 3235.5,8036.5 h70
  text "3" at 5724.84,8036.5 h70
  text "4" at 8231.51,8036.5 h70
  text "5" at 10730.5,8036.5 h70
  text "6" at 13235.5,8036.5 h70
  text "A" at -416.5,6893.5 h70
  text "A" at 14383.5,6893.5 h70
  text "B" at -416.5,4513.5 h70
  text "B" at 14383.5,4513.5 h70
  text "C" at -416.5,2138.5 h70
  text "C" at 14383.5,2138.5 h70
  text "PROJECT TITLE:" at 11343.5,277.5 h45
  text ".PRJ_Title" at 11393.5,144.17 h70
  text "DESIGNED FOR:" at 11343.5,-23.5 h45
  text ".PRJ_Customer" at 11393.5,-163.5 h70
  text "D" at -416.5,-231.5 h70
  text "D" at 14383.5,-231.5 h70
  text "FILE NAME:" at 11343.5,-323.5 h45
  text ".PCB_File_Name_No_Path" at 11393.5,-443.5 h70
  text "Texas Instruments (TI) and/or its licensors do not warrant the accuracy or completeness of this specification" at 6374,-605.34 h45
  text "ENGINEER:" at 11343.5,-613.5 h45
  text "LAYOUT BY:" at 12848.5,-613.5 h45
  text "or any information contained therein. TI and/or its licensors do not warrant that this design will meet" at 6329.01,-718 h45
  text ".PRJ_Engineer" at 11393.5,-768.49 h70
  text ".PCB_Layout" at 12899,-768.49 h70
  text "the specifications, will be suitable for your application or fit for any particular purpose, or will operate in" at 6329.01,-830.67 h45
  text ".Layer_Name" at 577,-858.49 h60
  text "ALTIUM DESIGNER VERSION:" at 12848.5,-923.5 h45
  text "an implementation. TI and/or its licensors do not warrant that the design is production worthy. You should" at 6329.01,-943.33 h45
  text "completely validate and test your design implementation to confirm the system functionality for your application." at 6374,-1056 h45
  text ".print_Scale" at 11393.5,-1056.83 h70
  text ".Application_BuildNumber" at 12899,-1056.83 h70
  text "1" at 739.84,-1263.5 h70
  text "2" at 3235.5,-1263.5 h70
  text "3" at 5724.84,-1263.5 h70
  text "4" at 8231.51,-1263.5 h70
  text "5" at 10730.5,-1263.5 h70
  text "6" at 13235.5,-1263.5 h70
M10 Fab Notes:
  drawing of 212 lines, arcs and shapes, not listed
  text "DESIGN INFORMATION" at 12381.02,6810 h60
  text "(REFER ALSO ARRAY/PANEL PROFILING INFORMATION)" at 12019.46,6648.29 h60
  text "BOARD SIZE" at 11333.46,6644 h60
  text "3450MIL" at 11795.78,6516.18 h60
  text "X" at 12301.46,6516.18 h60
  text "4950MIL" at 12532.78,6516.18 h60
  text "Number of Layers :" at 11736.46,6319 h60
  text "4" at 12831.27,6309 h60
  text "MIN. TRACK WIDTH:" at 11736.46,6180 h60
  text "5" at 12832.7,6180 h60
  text "MIL" at 12987.46,6180 h60
  text "4.5" at 12776.5,6049 h60
  text "MIN. CLEARANCE:" at 11736.46,6048 h60
  text "MIL" at 12987.46,6048 h60
  text "MIN. VIA PAD SIZE:" at 11736.46,5916 h60
  text "24" at 12802.71,5916 h60
  text "MIL" at 12987.46,5916 h60
  text "0.05mm (2MIL)" at 12431.46,5774.29 h60
  text "MINIMUM ANNULAR RING" at 11407.23,5770 h60
  text "EXTERNAL" at 13139.46,5770 h60
  text "PER" at 11607.23,5652 h60
  text "IPC-D-275 CLASS 2 LEVEL C" at 11827.23,5652 h60
  text "MIL, HOLES" at 13315.46,5539.71 h60
  text "+/-" at 12923,5539 h60
  text "+/-" at 13777,5539 h60
  text "REGISTRATION TOLERANCES:" at 11407.23,5534 h60
  text "METAL" at 12607,5534 h60
  text "5" at 13183.2,5534 h60
  text "3" at 14016.2,5534 h60
  text "MIL" at 14132.46,5534 h60
  text "MATERIAL:" at 11332.46,5324.54 h60
  text "FR-4 High Tg" at 12318.9,5184.21 h60
  text "FR-408" at 11753.46,5175.64 h60
  text "X" at 12165.46,5175.64 h60
  text "OTHER" at 13241.46,5175.64 h60
  text "62 MIL (1.6mm) +/-10%" at 12073.56,5012.92 h60
  text "THICKNESS:" at 11407.23,5008.64 h60
  text "OTHER" at 13358.46,5008.64 h60
  text "59.8" at 13696.5,5001 h60
  text "X" at 13233,4995 h60
  text "TOLERANCE:" at 11407.23,4850.64 h60
  text "X" at 12246.53,4850.64 h60
  text "ANSI IPC-6012 TYPE 3 CLASS 2" at 12433.48,4850.64 h60
  text "OTHER +/-" at 12433.46,4694.64 h60
  text "100ohm Differential top Layer 5mil trace width 7 mil spacing, 90ohm Differential 5.3 mil trace width 5 mil spacing on Bottom Layer" at -180,4610 h65
  text "BOW & TWIST:" at 11407.23,4537.64 h60
  text "X" at 12246.53,4537.64 h60
  text "ANSI IPC-6012 TYPE 3 CLASS 2" at 12433.48,4537.64 h60
  text "OTHER +/-" at 12433.46,4379.13 h60
  text "COPPER THICKNESS (FINISHED):" at 11332.46,4243.64 h60
  text "1.4MIL (1oz)" at 12212.46,4090.92 h60
  text "2MIL (1.4oz)" at 12979.46,4090.92 h60
  text "2.8MIL (2oz)" at 13706.46,4090.92 h60
  text "OUTER:" at 11689.46,4086.64 h60
  text "X" at 12084,4086 h60
  text "1.4MIL (1oz)" at 12212.46,3933.92 h60
  text "2.8MIL (2oz)" at 12979.46,3933.92 h60
  text "N/A" at 13706,3934.29 h60
  text "INNER SIGNAL:" at 11400.38,3929.64 h60
  text "X" at 12085.42,3929.64 h60
  text "DRILLING:" at 11332.46,3790.64 h60
  text "REFERENCE:" at 11407.23,3673.64 h60
  text "X" at 12055.46,3673.64 h60
  text "AS SHOWN" at 12242.46,3673.64 h60
  text "X" at 12956.46,3673.64 h60
  text "NC_DRILL FILES" at 13093.46,3673.64 h60
  text "PTH MIN COPPER THICKNESS:" at 11407.23,3515.64 h60
  text "X" at 12757.46,3515.64 h60
  text "1MIL" at 12894.46,3515.64 h60
  text "OTHER" at 13391.46,3515.64 h60
  text "BOARD FINISH:" at 11332.46,3356.64 h60
  text "SILKSCREEN:" at 11487.68,3238.64 h60
  text "X" at 12436.46,3238.64 h60
  text "TOP" at 12562.46,3238.64 h60
  text "X" at 12946.46,3238.64 h60
  text "BOTTOM" at 13073.46,3238.64 h60
  text "SILKSCREEN COLOR:" at 11487.68,3071.64 h60
  text "X" at 12435.42,3071.64 h60
  text "WHITE" at 12562.46,3071.64 h60
  text "OTHER" at 13073.46,3071.64 h60
  text "SOLDER RESIST COLOR:" at 11487.68,2901.64 h60
  text "X" at 12055.42,2742.44 h60
  text "GREEN" at 12182.46,2742.44 h60
  text "BLUE" at 12773.46,2742.44 h60
  text "OTHER" at 13311.46,2742.44 h60
  text "IMMERSION GOLD (ENIG)" at 12393.46,2553.92 h60
  text "ENEPIG" at 13731,2550.64 h60
  text "SURFACE FINISH:" at 11332.46,2549.64 h60
  text "X" at 12206.51,2549.64 h60
  text "IMM. TIN/SILVER OR EQUIV" at 11662,2392.64 h60
  text "OTHER" at 13093.46,2392.64 h60
  text "ARRAY/PANEL:" at 11332.46,2213.64 h60
  text "CUT AND TRIM PER MECH LAYER 1" at 12393.46,2209.35 h60
  text "N.C. ROUTE" at 12393.46,2057.64 h60
  text "X" at 13072.46,2057.64 h60
  text "V. SCORE" at 13259.46,2057.64 h60
  text "CERTIFICATION:" at 11332.46,1920.64 h60
  text "MATERIALS AND WORKMANSHIP FOR ALL PCBS" at 12057.46,1920.64 h60
  text "TO MEET OR EXCEED THE REQUIREMENTS OF:" at 12057.46,1822.64 h60
  text "X" at 11683.96,1686.13 h60
  text "ANSI IPC-A-600F CLASS ->" at 11822.96,1686.13 h60
  text "X" at 13462.02,1686.13 h60
  text "2" at 13580.96,1686.14 h60
  text "1" at 13265.96,1684.64 h60
  text "3" at 13934.96,1684.64 h60
  text "X" at 11686.02,1526.64 h60
  text "UL 94V-0" at 11822.96,1526.64 h60
  text "X" at 12498.02,1526.64 h60
  text "RoHS" at 12634.96,1526.64 h60
  text "OTHER" at 13279.36,1526.64 h60
  text "PER ORDER" at 13676.42,1526.64 h60
  text "ADDITIONAL REQUIREMENTS:" at 11332.46,1385.64 h60
  text "MICROSECTION:" at 11407.23,1270.64 h60
  text "YES" at 12312.96,1270.64 h60
  text "REQUIRED" at 13174.46,1114.49 h60
  text "BARE BOARD ELEC. TEST:" at 11407.23,1111.64 h60
  text "NONE" at 12712.96,1111.64 h60
  text "X" at 13047.46,1111.64 h60
  text "PER ORDER" at 13766.46,1111.64 h60
  text "MANUFACTURER'S UL:" at 11407.23,954.64 h60
  text "RAIL" at 12572.96,950.35 h60
  text "METAL" at 13064.77,950.35 h60
  text "X" at 13440,950 h60
  text "SILK" at 13576.46,950.35 h60
  text ".Layer_Name" at 577,-858.49 h60
M11 Gerber Information:
  lines w10: -292,-930.17 6308,-930.17 ; -292,-726.83 6310,-726.83 ; -292,-523.5 -292,-1133.5 3713,-1133.5 6310,-1133.5 6310,-523.5 -291.5,-523.5 -291.5,-1133.5 1284,-1133.5 ; 2173,-1133.5 2173,-523.5 ; 3440,-726.83 3440,-523.5 ; 4280,-726.83 4280,-523.5 ; 4902,-1140 4902,-937.17
  text "ALL ARTWORK VIEWED FROM TOP SIDE" at -228.5,-655.67 h60
  text "BOARD #:" at 2248,-655.67 h60
  text ".PRJ_Number" at 2793.5,-655.67 h60
  text "REV:" at 3638,-655.67 h60
  text ".PCB_Rev" at 3929.5,-655.67 h60
  text "SVN REV:" at 4476,-655.67 h60
  text ".VersionControl_RevNumber" at 4982,-655.67 h60
  text "LAYER NAME =" at -228.5,-858.49 h60
  text "PLOT NAME =" at -228.5,-1064.34 h60
  text ".plot_File_Name" at 577,-1064.34 h60
  text "GENERATED    :" at 2250,-1064.34 h60
  text ".Print_Date" at 3119.5,-1064.34 h60
  text ".Print_Time" at 3848.5,-1064.34 h60
  text "TEXAS INSTRUMENTS" at 5113,-1064.34 h60
M12 Stackup:
  lines w6: 10964,7691.88 14228,7691.88 ; 10964,7804.48 14228,7804.48 ; 10904,6971.5 ccw(c10940,6971.5) 10940,6935.5 14252,6935.5 ccw(c14252,6971.5) 14288,6971.5 14288,7904 ccw(c14252,7904) 14252,7940 10940,7940 ccw(c10940,7904) 10904,7904 10904,6971.5
  text "Layer Stack Up Detail for: ISE4012 RevE1.PcbDoc" at 10964,7833.64 h52
  text "Layer" at 10964,7762.48 h26
  text "Gerber" at 11663.8,7762.48 h26
  text "Copper" at 12017.85,7762.48 h26
  text "Dielectric" at 12414.35,7762.48 h26
  text "Dielectric" at 12829.04,7762.48 h26
  text "Dielectric" at 13348.9,7762.48 h26
  text "Dielectric" at 13763.6,7762.48 h26
  text "Name" at 10964,7710.48 h26
  text "Document" at 11663.8,7710.48 h26
  text "Thickness" at 12017.85,7710.48 h26
  text "Height" at 12414.35,7710.48 h26
  text "Material" at 12829.04,7710.48 h26
  text "Constant" at 13348.9,7710.48 h26
  text "Type" at 13763.6,7710.48 h26
  text "Top Solder Mask" at 10964,7636.56 h36
  text "(.GTS)" at 11663.8,7636.56 h36
  text "0.4mil" at 12414.35,7636.56 h36
  text "Solder Resist" at 12829.04,7636.56 h36
  text "3.50" at 13348.9,7636.56 h36
  text "Top Layer" at 10964,7531.92 h36
  text "(.GTL)" at 11663.8,7531.92 h36
  text "1.4mil" at 12017.85,7531.92 h36
  text "5.2mil" at 12414.35,7479.6 h36
  text "370HR" at 12829.04,7479.6 h36
  text "4.80" at 13348.9,7479.6 h36
  text "PrePreg" at 13763.6,7479.6 h36
  text "InternalPlane1" at 10964,7427.29 h36
  text "(.GP1)" at 11663.8,7427.29 h36
  text "1.4mil" at 12017.85,7427.29 h36
  text "43mil" at 12414.35,7374.97 h36
  text "370HR" at 12829.04,7374.97 h36
  text "4.80" at 13348.9,7374.97 h36
  text "Core" at 13763.6,7374.97 h36
  text "MidLayer1" at 10964,7322.65 h36
  text "(.G1)" at 11663.8,7322.65 h36
  text "1.4mil" at 12017.85,7322.65 h36
  text "5.2mil" at 12414.35,7270.33 h36
  text "370HR" at 12829.04,7270.33 h36
  text "4.80" at 13348.9,7270.33 h36
  text "PrePreg" at 13763.6,7270.33 h36
  text "Bottom Layer" at 10964,7218.02 h36
  text "(.GBL)" at 11663.8,7218.02 h36
  text "1.4mil" at 12017.85,7218.02 h36
  text "Bottom Solder Mask" at 10964,7113.38 h36
  text "(.GBS)" at 11663.8,7113.38 h36
  text "0.4mil" at 12414.35,7113.38 h36
  text "Solder Resist" at 12829.04,7113.38 h36
  text "3.50" at 13348.9,7113.38 h36
  text ".Layer_Name" at 577,-858.49 h60
M13 Component Bodies Top:
  text ".Layer_Name" at 577,-858.49 h60
M14 Component Bodies Bottom:
  text ".Layer_Name" at 577,-858.49 h60
M15 Courtyards Top:
  text ".Layer_Name" at 577,-858.49 h60
M16 Courtyards Bottom:
  text ".Layer_Name" at 577,-858.49 h60
Drill Drawing:
  text ".legend" at 5145,690 h60
  text "Drill Table" at 5147.5,540.5 h60
  text ".Layer_Name" at 577,-858.49 h60

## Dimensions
0,0 to 0,3450 on M2 Board Dimensions
0,0 to 4950,0 on M2 Board Dimensions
